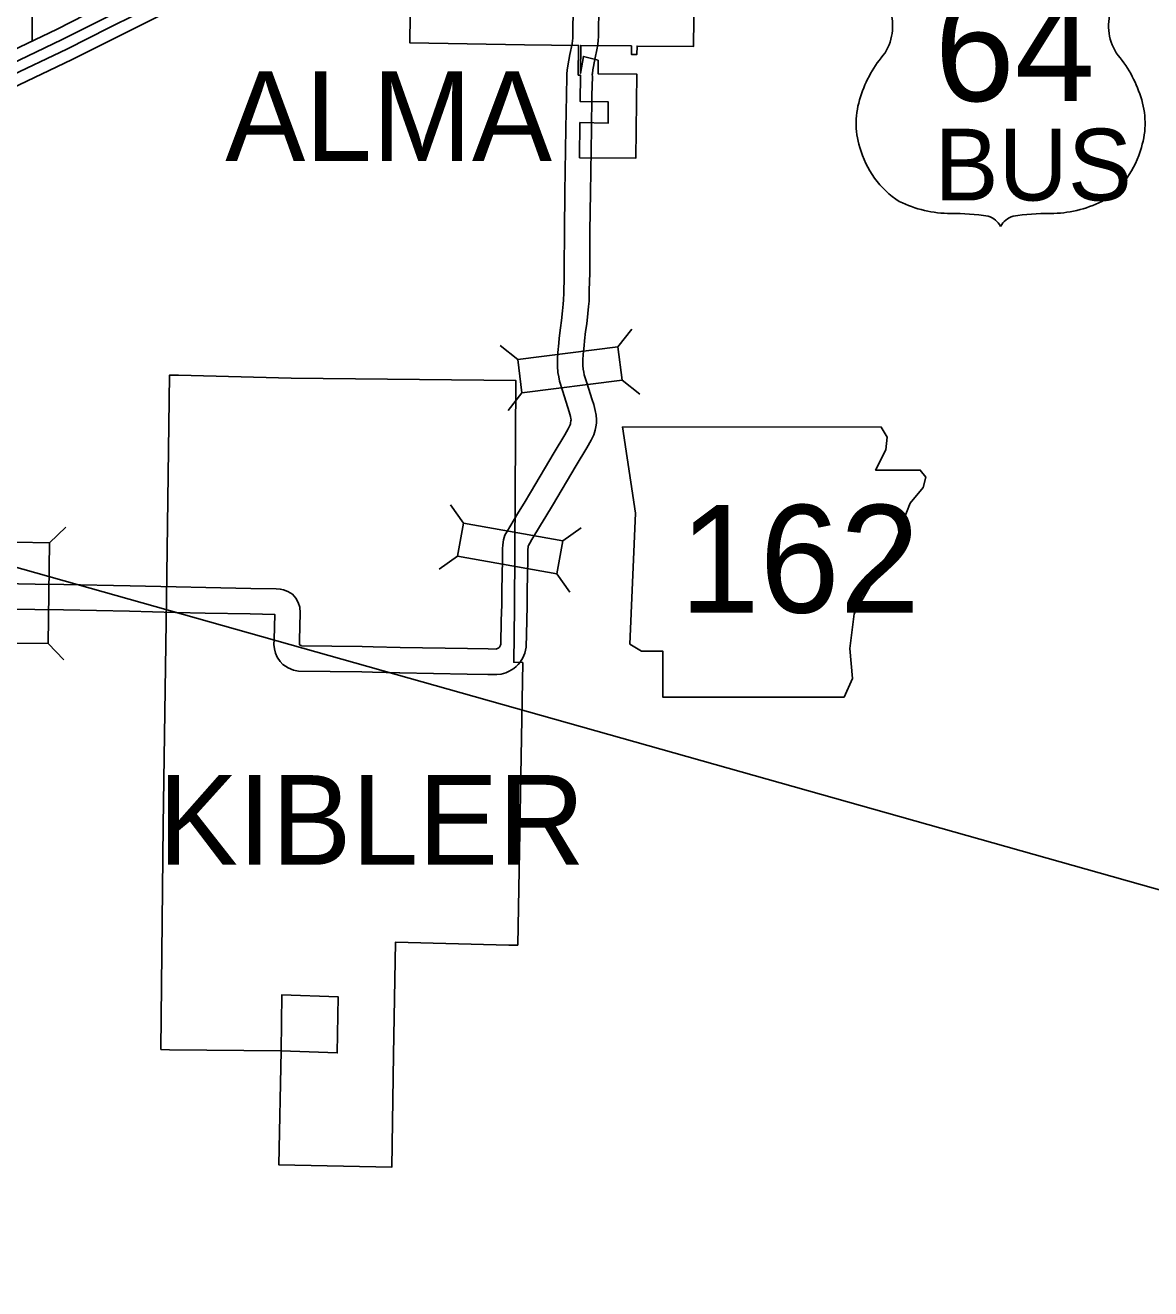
# Model space of a CAD drawing. Extents: x 535214 to 694517, y 381272 to 484355.
# Drawn here: x 552790 to 559413, y 456216 to 463649 of the extents above; entities that cross this region are included whole.
import ezdxf

# ---------------------------------------------------------------- set-up
doc = ezdxf.new("R2010")
doc.units = 0
for name, color, linetype in [('1', 7, 'Continuous'), ('Level 10', 7, 'Continuous'), ('Level 15', 7, 'Continuous'), ('Level 20', 7, 'Continuous'), ('Level 21', 7, 'Continuous'), ('Level 22', 7, 'Continuous'), ('Level 6', 7, 'Continuous')]:
    doc.layers.add(name, color=color, linetype=linetype)

msp = doc.modelspace()

# ---------------------------------------------------------------- linework, layer by layer
at = {"layer": '1'}
msp.add_line((546782.5, 462138.9), (567784.7, 456216.2), dxfattribs=at)
at = {"layer": 'Level 10'}
for points in [[(556164.5, 463726.1), (556162, 463623.5), (556162.4, 463582), (556161.8, 463558.6), (556158.6, 463537.4), (556155.3, 463513.7), (556141, 463447.4), (556130.3, 463385.7), (556127, 463365.2), (556126.3, 463358.8), (556126.7, 463346.8), (556123.7, 463235.5), (556121.2, 463039), (556119.5, 462914), (556115.6, 462663.3), (556112.6, 462437.7), (556111, 462214.6), (556110.9, 462170.7), (556110.1, 462160.7), (556107.9, 462069.2), (556107.1, 462026.5), (556104.7, 461994.5), (556100.4, 461953.3), (556094.6, 461892.5), (556087.2, 461847.1), (556080.6, 461793.4), (556078.1, 461764.3), (556073.1, 461712.9), (556071.6, 461680.3), (556071.2, 461647.9), (556072.8, 461626.6), (556076.2, 461609), (556079.2, 461593), (556094.5, 461546), (556125.5, 461445.7), (556134.4, 461418.5), (556144, 461383), (556149.9, 461354.8), (556151.2, 461329.8), (556150.5, 461307.8), (556147.2, 461287.4), (556144, 461266.2), (556134.4, 461240.1), (556119.3, 461207.2), (556095, 461163.4), (556030.7, 461058.2), (555891.5, 460823.6), (555852.9, 460759.7), (555821.3, 460707.6), (555770.4, 460623.6), (555758.2, 460601.5), (555750.3, 460587.8), (555749.9, 460586.4), (555748.4, 460577.4), (555747.9, 460565.9), (555747.9, 460505.2), (555743.6, 460322), (555743.2, 460237.4), (555741, 460144.7), (555737.5, 459990), (555729.6, 459955.8), (555717.5, 459926.8), (555701.4, 459903), (555689.7, 459887.9), (555677.8, 459876), (555665.2, 459864.6), (555636.7, 459849.1), (555618.1, 459840.3), (555589.5, 459830.7), (555564.4, 459829), (555511.2, 459829.9), (555390.4, 459831.6), (554993, 459838.4)], [(556014.5, 463728.7), (556012, 463624.6), (556012.4, 463583.1), (556012.1, 463571.6), (556010.2, 463558.9), (556007.5, 463540), (555993.8, 463476.1), (555982.4, 463410.7), (555978.1, 463384.3), (555976.1, 463363.6), (555976.6, 463346.6), (555973.7, 463238.5), (555971.2, 463041), (555969.5, 462916.2), (555965.6, 462665.4), (555962.6, 462439.2), (555961, 462215.3), (555960.9, 462177), (555960.2, 462168.7), (555958, 462072.6), (555957.2, 462033.6), (555955.3, 462007.8), (555951.1, 461968.2), (555945.8, 461911.6), (555938.7, 461868.5), (555931.3, 461809), (555928.7, 461777.8), (555923.5, 461723.7), (555921.6, 461684.8), (555921.1, 461643.2), (555923.8, 461606.6), (555928.9, 461580.8), (555933.6, 461556), (555951.5, 461500.7), (555982.5, 461400.2), (555990.6, 461375.5), (555998, 461348.1), (556000.7, 461335.4), (556001.1, 461328.1), (556000.9, 461322), (555999, 461310.5), (555998, 461303.7), (555995.7, 461297.5), (555985.3, 461275), (555965.4, 461238.9), (555902.2, 461135.6), (555762.8, 460900.7), (555724.5, 460837.3), (555693, 460785.3), (555640.6, 460698.8), (555627.5, 460675.2), (555612.4, 460648.9), (555603.6, 460621.4), (555599, 460592.9), (555597.9, 460569.6), (555597.9, 460506.9), (555593.6, 460324.2), (555593.2, 460239.5), (555591, 460148.2), (555587.9, 460008.6), (555586.3, 460002), (555584.9, 459998.6), (555579.8, 459991), (555576.9, 459987.3), (555568.7, 459982.8), (555562.1, 459979.7), (555560.2, 459979.1), (555513.5, 459979.9), (555392.7, 459981.6), (554995.6, 459988.4)], [(554996.4, 459988.4), (554836.1, 459992.8), (554772.2, 459994.4), (554414.5, 459999), (554412.5, 459999.4), (554407.2, 460001.5), (554405.2, 460002.8), (554405.2, 460002.9), (554403.7, 460008.8), (554403.1, 460013.8), (554403.6, 460031.5), (554407.6, 460192.4), (554405.4, 460224.8), (554395.8, 460253.6), (554382.2, 460279.5), (554361.6, 460303.1), (554335.2, 460318.7), (554310.1, 460327.9), (554290.4, 460332.3), (554266.1, 460333.3), (554116, 460336.3), (553851.8, 460341.2), (553676.9, 460344.9), (553407.1, 460351.2), (553017.3, 460359.2), (552847.4, 460361.9), (552354.9, 460370.7)], [(554992.2, 459838.4), (554832.2, 459842.9), (554769.4, 459844.4), (554397.5, 459849.2), (554368.8, 459855.4), (554336.7, 459868), (554305.8, 459889.1), (554290.2, 459905.3), (554272.2, 459931.7), (554262.5, 459955.3), (554256.1, 459980.9), (554252.7, 460006.5), (554253.7, 460035.8), (554257.4, 460183.5), (554113.1, 460186.4), (553848.8, 460191.2), (553673.6, 460195), (553403.8, 460201.2), (553014.6, 460209.2), (552844.9, 460211.9), (552352, 460220.7), (551688.7, 460234.5)]]:
    msp.add_lwpolyline(points, dxfattribs=at)
at = {"layer": 'Level 15'}
for points in [[(548562.9, 461621.7), (548645.1, 461654.2), (548810.9, 461725.9), (549316.1, 461954.3), (549999.3, 462258.7), (550500.7, 462484.6), (550868, 462651.2), (551274.6, 462835.7), (551650, 463001.7), (551926.9, 463130.7), (552279.7, 463296.2), (552622.9, 463457.5), (552976.7, 463626.4), (553227, 463752.4), (553529.4, 463902.7)], [(548132.1, 461237), (548230.4, 461317.2), (548372.8, 461434.8), (548448.5, 461491), (548517.7, 461530), (548671.4, 461590.6), (548838.8, 461663), (549344.2, 461891.6), (550027.4, 462195.9), (550529, 462422), (550896.4, 462588.6), (551302.7, 462773), (551678.5, 462939.1), (551956, 463068.4), (552309, 463233.9), (552652.4, 463395.4), (553006.9, 463564.7), (553257.7, 463690.9), (553560, 463841.1)], [(548174.7, 461191.1), (548270.1, 461268.9), (548411.4, 461385.6), (548482.6, 461438.5), (548544.6, 461473.4), (548695.3, 461532.9), (548864, 461605.9), (549369.8, 461834.5), (550053, 462138.9), (550554.7, 462365), (550922.2, 462531.6), (551328.3, 462716), (551704.3, 462882.2), (551982.5, 463011.8), (552335.5, 463177.4), (552679.1, 463338.9), (553034.4, 463508.6), (553285.7, 463635), (553587.8, 463785.1)], [(548192.5, 461116.8), (548313.7, 461215.8), (548453.8, 461331.4), (548520.1, 461380.7), (548574.2, 461411.2), (548721.5, 461469.3), (548891.8, 461543), (549398, 461771.8), (550081.1, 462076.2), (550583.1, 462302.4), (550950.6, 462469), (551356.4, 462653.2), (551732.7, 462819.6), (552011.6, 462949.5), (552364.7, 463115.1), (552708.6, 463276.7), (553064.7, 463446.9), (553316.4, 463573.5), (553618.4, 463723.6)]]:
    msp.add_lwpolyline(points, dxfattribs=at)
at = {"layer": 'Level 20'}
for p, q in [((552829.6, 463557.9), (552832.3, 464039)), ((556277, 461756.6), (556358.1, 461860.8)), ((555687.6, 461683.1), (555583.4, 461764.2)), ((556301.5, 461560.2), (556405.7, 461479.1)), ((555712.1, 461486.7), (555631, 461382.5)), ((555367.7, 460720), (555292, 460828.2)), ((552932.8, 460605.1), (553027.4, 460697.1)), ((555952.6, 460616.7), (556060.8, 460692.4)), ((555333.3, 460525.1), (555225.1, 460449.4)), ((555918.2, 460421.7), (555993.9, 460313.5)), ((552924.4, 460011.2), (553016.4, 459916.5))]:
    msp.add_line(p, q, dxfattribs=at)
for points in [[(556277, 461756.6), (555687.6, 461683.1), (555712.1, 461486.7), (556301.5, 461560.2)], [(555333.3, 460525.1), (555918.2, 460421.7), (555952.6, 460616.7), (555367.7, 460720)], [(552734.8, 460607.9), (552726.4, 460014), (552924.4, 460011.2), (552932.8, 460605.1)]]:
    msp.add_lwpolyline(points, close=True, dxfattribs=at)
at = {"layer": 'Level 21'}
msp.add_lwpolyline([(556304.9, 461285.9), (556381.1, 460778.3), (556347.2, 460008.6), (556414.9, 459966.3), (556541.8, 459966.3), (556541.8, 459695.6), (557607.6, 459695.6), (557658.4, 459805.5), (557641.5, 459983.2), (557666.8, 460186.2), (557759.9, 460346.9), (557819.1, 460465.3), (557903.7, 460592.2), (557954.4, 460727.6), (557996.7, 460837.5), (558072.9, 460930.6), (558089.8, 460989.8), (558055.9, 461032.1), (557793.7, 461032.1), (557852.9, 461150.5), (557861.4, 461226.7), (557826.3, 461285.1)], close=True, dxfattribs=at)
at = {"layer": 'Level 22'}
for centre, radius, start, end in [((557585.4, 463645.5), 308.3, 328.81046, 21.21077), ((559472.9, 463645.5), 308.3, 158.78923, 211.18954), ((558391.5, 463013.7), 719.2, 138.95648, 162.69135), ((558666.7, 463013.7), 719.2, 17.30865, 41.04352), ((558154.1, 463072.6), 475.2, 160.95764, 197.38186), ((558904.2, 463072.6), 475.2, 342.61814, 19.04236), ((558231.4, 463073.9), 549.8, 195.10743, 237.13119), ((558826.8, 463073.9), 549.8, 302.86881, 344.89257), ((558241.7, 463247.1), 706, 244.07708, 269.57785), ((558816.6, 463247.1), 706, 270.42215, 295.92292), ((558258, 461248), 1293.3, 81.19416, 90.95387), ((558800.2, 461248), 1293.3, 89.04613, 98.80584), ((558419.7, 462407.5), 123.9, 28.03422, 72.98637), ((558638.5, 462407.5), 123.9, 107.01363, 151.96578)]:
    msp.add_arc(centre, radius, start, end, dxfattribs=at)
at = {"layer": 'Level 6'}
for points in [[(556729, 464181.6), (556721, 463523), (556389.6, 463526.8), (556389.1, 463477.4), (556356.3, 463477.7), (556356.8, 463527.2), (556058.2, 463530.6), (556056.6, 463365.2), (556074.4, 463465.9), (556160.2, 463442.9), (556160.2, 463364.1), (556387.8, 463361.8), (556386, 463196.8), (556382.4, 462866.7), (556051.9, 462869), (556053.9, 463075.9), (556220.6, 463073), (556220.6, 463198.3), (556055.1, 463199.8), (556056.6, 463355.6), (556044.1, 463355.4), (556045.7, 463530.7), (555726.9, 463534.3), (555053.2, 463544.6), (555056.6, 463875.5)], [(555716.9, 459900.9), (555664.4, 459901.5), (555667.9, 460222.5), (555676.1, 461560), (554354.8, 461572.8), (553691.8, 461589.6), (553639.3, 461591), (553621.3, 460270.2), (553601.5, 458943.9), (553586.8, 457622.9)], [(555687.4, 458237.4), (555716.9, 459900.9)], [(554955.9, 457591.2), (554962.3, 457923.6), (554968.7, 458255.9), (555634.9, 458237.8), (555687.4, 458237.4)], [(554295.7, 457615), (554299.1, 457944.6), (554630.7, 457934.1), (554625.9, 457603.1), (554295.7, 457615)], [(553586.8, 457622.9), (553639.3, 457622.3), (554295.7, 457615)], [(554295.7, 457615), (554282.6, 456944.7), (554945.8, 456930.7), (554955.9, 457591.2)]]:
    msp.add_lwpolyline(points, dxfattribs=at)

# ---------------------------------------------------------------- texts
at = {"layer": 'Level 21'}
msp.add_text('162', height=633.6, dxfattribs=at).set_placement((556639.7, 460193.5))
at = {"layer": 'Level 22'}
for s, height, p in [('64', 633.6, (558140.9, 463202.9)), ('BUS', 422.4, (558140.4, 462618))]:
    msp.add_text(s, height=height, dxfattribs=at).set_placement(p)
at = {"layer": 'Level 6'}
for s, p in [('ALMA', (553966.4, 462850.8)), ('KIBLER', (553570.9, 458709.9))]:
    msp.add_text(s, height=528, dxfattribs=at).set_placement(p)

doc.saveas('drawing.dxf')
